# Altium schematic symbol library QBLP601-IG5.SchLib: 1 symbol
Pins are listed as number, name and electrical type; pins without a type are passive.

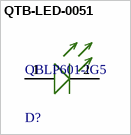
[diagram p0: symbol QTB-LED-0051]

## QTB-LED-0051
designator D?, comment QBLP601-IG5
LED GREEN CLEAR 0603 SMD; Manufacturer: QT Brightek (QTB); Lens Size: 0.8mm; Luminous Intensity: 100mcd; Test Current: 5mA; Lens Color: Colorless; Lens Style: Flat; Forward Voltage: 2.9V; Wavelength - Dominant: 525nm
footprint QBLP601-IG5-MFG
pins: 1 ANODE (+), 2 CATHODE (-)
